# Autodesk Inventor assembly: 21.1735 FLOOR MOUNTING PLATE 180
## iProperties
Created: 2007-04
Part Number: 21.1735 FLOOR MOUNTING PLATE 180
Document SubType Name: Assembly
Designer: Andy Moles
Author: Andy Moles
